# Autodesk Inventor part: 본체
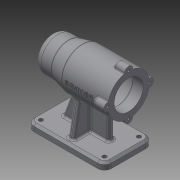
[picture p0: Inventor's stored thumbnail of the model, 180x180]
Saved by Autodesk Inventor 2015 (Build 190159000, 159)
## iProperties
Created: 2019-07
Part Number: 본체
Material: 일반
Document SubType Name: Modeling
Designer: cad-11
Density: 1 g/cm^3
Appearance: 기본값
Mass: 238.729 g
Surface Area: 654.854 cm^2
Volume: 238.729 cm^3
Author: cad-11
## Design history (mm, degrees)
sketch "스케치2"
  geometry: L1 (-56, 35)-(56, 35); L2 (56, 35)-(56, -35); L3 (56, -35)-(-56, -35); L4 (-56, -35)-(-56, 35); L5 (-56, 35)-(56, -35); L6 (56, 35)-(-56, -35); 1 further point
  constraints: 12 end point, 2 midpoint, 2 parallel, 1 horizontal, 1 perpendicular
  dimensions: "d4" = 112 distance of L1.start L1.end; "d5" = 70 distance of L1.end L2.end
extrude "돌출2" new body sketch "스케치2" distance "d6" = 10; taper "d7" = 0 deg
fillet "모깎기1" dims "d8" = 10
sketch "스케치3"
  geometry: A1 r 10 centre (-46, 25) between (-46, 35) and (-56, 25) reference; A2 r 10 centre (-46, -25) between (-56, -25) and (-46, -35) reference; A3 r 10 centre (46, -25) between (46, -35) and (56, -25) reference; A4 r 10 centre (46, 25) between (56, 25) and (46, 35) reference; 1 further point
hole "구멍1" sketch "스케치3" at (-46, 25), (-46, -25), (46, -25), (46, 25) diameter "d9" = 6; stored, may be unused: countersink angle "d13" = 90 deg, drill point angle "d15" = 118 deg; dims "d10" = 8, "d11" = 4, "d12" = 2, "d14" = 11
sketch "스케치4"
  geometry: L1 (-56, 25)-(-56, -25) reference; L2 (-46, -35)-(46, -35) reference; L3 (56, -25)-(56, 25) reference; L4 (46, 35)-(-46, 35) reference; L5 (-36, 4)-(31, 4); L6 (31, 4)-(31, -4); L7 (31, -4)-(-36, -4); L8 (-36, -4)-(-36, 4); L9 (-4, 28)-(4, 28); L10 (4, 28)-(4, -28); L11 (4, -28)-(-4, -28); L12 (-4, -28)-(-4, 28); 3 further points
  constraints: 16 end point, 4 parallel, 2 horizontal, 2 midpoint, 2 perpendicular, 1 horizontal alignment, 1 vertical alignment
  dimensions: "d16" = 25 distance between parallel lines of L3 L6; "d17" = 8 distance between parallel lines of L7 L5; "d18" = 20 distance between parallel lines of L1 L8; "d19" = 4 distance from line of point (0, 0) L12; "d20" = 7 distance between parallel lines of L2 L11; "d21" = 7 distance between parallel lines of L4 L9
extrude "돌출3" join sketch "스케치4" distance "d22" = 70; taper "d23" = 0 deg
feature "면 기울기1" dims angle "d24" = 10 deg
feature "면 기울기2" dims angle "d25" = 10 deg
feature "면 기울기3" dims angle "d26" = 20 deg
sketch "스케치15"
  geometry: L1 (56, 10)-(56, 0) reference; L2 (56, 0)-(-56, 0) reference; L3 (-56, 0)-(-56, 10) reference; L4 (-56, 10)-(-31, 10) reference; L5 (-31, 10)-(-31, 80) reference; L6 (-31, 80)-(10.522, 80) reference; L7 (10.522, 80)-(36, 10) reference; L8 (36, 10)-(56, 10) reference; L9 (56, 80)-(-56, 80); L10 (-56, 80)-(-56, 110); L11 (-56, 110)-(11, 110); L12 (11, 110)-(31, 105); L13 (31, 105)-(56, 105); L14 (56, 105)-(56, 80); 3 further points
  constraints: 12 end point, 3 perpendicular, 2 midpoint, 1 collinear, 1 horizontal, 1 parallel, 1 vertical alignment
  dimensions: "d39" = 25 distance of L13.end L9.start; "d40" = 30 distance between parallel lines of L9 L11; "d41" = 25 distance from line of L12.end L14; "d42" = 45 distance from line of L11.end L14; "d43" = 112 distance between parallel lines of L10 L14
revolve "회전1" sketch "스케치15" stored, may be unused: angle "d44" = 90 deg
sketch "스케치17"
  geometry: C1 r 6 at (0, 30); 2 further points
  constraints: 2 vertical alignment, 1 centre point, 1 other
  dimensions: "d45" = 12 diameter of C1
extrude "돌출8" join sketch "스케치17" distance "d46" = 16; taper "d47" = 0 deg
fillet "모깎기2" dims "d51" = 3
fillet "모깎기3" dims "d52" = 3
fillet "모깎기4" dims "d53" = 1
sketch "스케치18"
  geometry: A1 r 6 centre (-60, 0) between (-60.171, 5.998) and (-60.171, -5.998) reference; 1 further point
hole "구멍2" sketch "스케치18" at (-60, 0) diameter "d54" = 3.242; stored, may be unused: countersink angle "d58" = 90 deg, drill point angle "d60" = 118 deg; dims "d55" = 8, "d56" = 4, "d57" = 2, "d59" = 11
sketch "스케치19"
  geometry: C1 r 21 at (-30, 0); A1 r 30 centre (-30, 0) between (-59.226, -6.771) and (-36.771, -29.226) reference; 1 further point
  constraints: 1 centre point, 1 coincident
  dimensions: "d64" = 42 diameter of C1
extrude "돌출9" cut sketch "스케치19" distance "d65" = 15; taper "d66" = 0 deg
sketch "스케치20"
  geometry: C1 r 21 at (0, 0) reference; C2 r 24 at (0, 0); 1 further point
  constraints: 1 centre point, 1 coincident
  dimensions: "d67" = 48 diameter of C2
extrude "돌출10" cut sketch "스케치20" distance "d68" = 54; taper "d69" = 0 deg
sketch "스케치21"
  geometry: C1 r 24 at (0, 0) reference; C2 r 21 at (0, 0); 1 further point
  constraints: 1 centre point, 1 coincident
  dimensions: "d70" = 42 diameter of C2
extrude "돌출11" cut sketch "스케치21" distance "d71" = 12; taper "d72" = 0 deg
sketch "스케치22"
  geometry: C1 r 21 at (0, 0) reference; C2 r 17.5 at (0, 0); 1 further point
  constraints: 1 centre point, 1 coincident
  dimensions: "d73" = 35 diameter of C2
extrude "돌출12" cut sketch "스케치22" distance "d74" = 18; taper "d75" = 0 deg
sketch "스케치23"
  geometry: C1 r 17.5 at (0, 0) reference; C2 r 16 at (0, 0); 1 further point
  constraints: 1 centre point, 1 coincident
  dimensions: "d76" = 32 diameter of C2
extrude "돌출13" cut sketch "스케치23" distance "d77" = 4; taper "d78" = 0 deg
sketch "스케치24"
  geometry: C1 r 16 at (0, 0) reference; C2 r 10.5 at (0, 0); 1 further point
  constraints: 1 centre point, 1 coincident
  dimensions: "d79" = 21 diameter of C2
extrude "돌출14" cut sketch "스케치24" distance "d80" = 3; taper "d81" = 0 deg
fillet "모깎기5" dims "d82" = 3
fillet "모깎기6" dims "d83" = 10
fillet "모깎기7" dims "d84" = 3
fillet "모깎기8" dims "d85" = 3
fillet "모깎기9" dims "d86" = 3
fillet "모깎기10" dims "d87" = 3
fillet "모깎기11" dims "d88" = 3
chamfer "모따기1" distance "d89" = 3; stored, may be unused: second distance "d90" = 2, angle "d91" = 45 deg
fillet "모깎기12" dims "d92" = 3
fillet "모깎기13" dims "d93" = 0.3
node "작업 평면1"
sketch "스케치25"
  geometry: L1 (33.5, 6.771)-(33.5, 29.226) reference; L2 (33.5, 5.998)-(33.5, -5.998) reference; 3 further points
  constraints: 1 horizontal alignment, 1 midpoint, 1 other
  dimensions: "d98" = 42 distance from line of L1 point (-8.5, 0)
feature "엠보싱1" sketch "스케치25" dims "d95" = 0.5, "d96" = 0
node "솔리드2"
pattern_circular "원형 패턴1" dims angle "d49" = 360 deg
pattern_circular "원형 패턴2" dims angle "d62" = 360 deg
node "절단 모서리 투영6"
